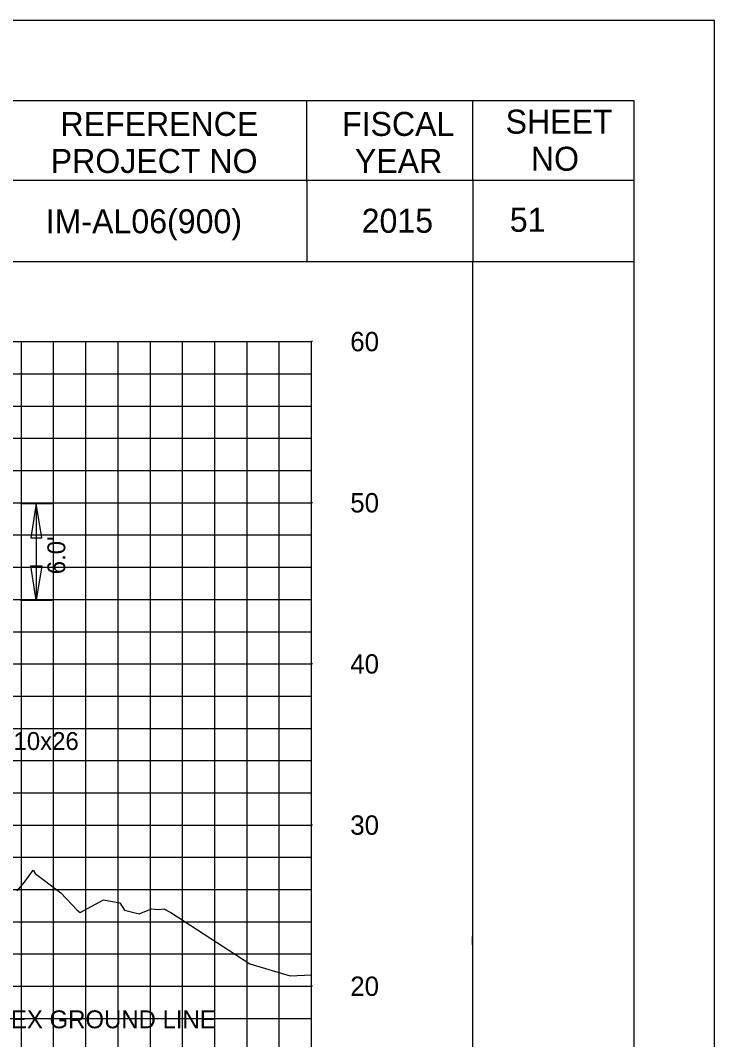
# Model space of a CAD drawing. Extents: x 2193008 to 2198143, y 1236112 to 1237864.
# Drawn here: x 2195154.8 to 2195197.9, y 1237274.8 to 1237338 of the extents above; entities that cross this region are included whole.
import ezdxf

# ---------------------------------------------------------------- set-up
doc = ezdxf.new("R2010")
doc.units = 0
for name, color, linetype in [('2', 7, 'Continuous'), ('31', 7, 'Continuous'), ('60', 7, 'Continuous'), ('ANNO-SHT', 7, 'Continuous'), ('GSDIMS', 7, 'Continuous'), ('Level 55', 7, 'Continuous'), ('Level 6', 7, 'Continuous'), ('M-ROADS', 7, 'Continuous'), ('SHT-BNDRY', 7, 'Continuous')]:
    doc.layers.add(name, color=color, linetype=linetype)

msp = doc.modelspace()

# ---------------------------------------------------------------- linework, layer by layer
msp.add_lwpolyline([(2194882.86, 1237133.046), (2195182.86, 1237133.046), (2195182.86, 1237323.046), (2194882.86, 1237323.046)], close=True)
at = {"layer": '2'}
msp.add_lwpolyline([(2195182.826, 1237281.186), (2195182.835, 1237280.187)], dxfattribs=at)
msp.add_lwpolyline([(2195182.826, 1237281.186), (2195182.835, 1237280.187)], dxfattribs=at)
at = {"layer": '60'}
for p, q in [((2195172.86, 1237258.106), (2195172.86, 1237318.106)), ((2195172.92, 1237318.106), (2195172.86, 1237318.106)), ((2195172.92, 1237308.106), (2195172.86, 1237308.106)), ((2195172.92, 1237298.106), (2195172.86, 1237298.106)), ((2195172.92, 1237288.106), (2195172.86, 1237288.106)), ((2195172.92, 1237278.106), (2195172.86, 1237278.106))]:
    msp.add_line(p, q, dxfattribs=at)
at = {"layer": 'GSDIMS'}
for p, q in [((2195154.801, 1237308.062), (2195156.769, 1237308.062)), ((2195155.785, 1237308.062), (2195155.785, 1237302.068)), ((2195154.801, 1237302.068), (2195156.769, 1237302.068))]:
    msp.add_line(p, q, dxfattribs=at)
for points in [[(2195155.785, 1237308.062), (2195155.437, 1237305.934), (2195156.132, 1237305.934)], [(2195155.785, 1237302.068), (2195155.437, 1237304.197), (2195156.132, 1237304.197)]]:
    msp.add_lwpolyline(points, close=True, dxfattribs=at)
at = {"layer": 'Level 6'}
for p, q in [((2195172.57, 1237328.038), (2195172.57, 1237333.038)), ((2195182.86, 1237328.168), (2195182.86, 1237333.038)), ((2195192.863, 1237328.097), (2195153.407, 1237328.097)), ((2195182.86, 1237328.168), (2195182.86, 1237323.046)), ((2195172.57, 1237328.038), (2195172.57, 1237323.046)), ((2195192.863, 1237323.046), (2195154.617, 1237323.046))]:
    msp.add_line(p, q, dxfattribs=at)
at = {"layer": 'M-ROADS'}
for p, q in [((2195042.86, 1237318.106), (2195172.86, 1237318.106)), ((2195154.86, 1237258.106), (2195154.86, 1237318.106)), ((2195156.86, 1237258.106), (2195156.86, 1237318.106)), ((2195158.86, 1237258.106), (2195158.86, 1237318.106)), ((2195160.86, 1237258.106), (2195160.86, 1237318.106)), ((2195162.86, 1237258.106), (2195162.86, 1237318.106)), ((2195164.86, 1237258.106), (2195164.86, 1237318.106)), ((2195166.86, 1237258.106), (2195166.86, 1237318.106)), ((2195168.86, 1237258.106), (2195168.86, 1237318.106)), ((2195170.86, 1237258.106), (2195170.86, 1237318.106)), ((2195172.86, 1237258.106), (2195172.86, 1237318.106)), ((2195042.86, 1237316.106), (2195172.86, 1237316.106)), ((2195042.86, 1237314.106), (2195172.86, 1237314.106)), ((2195042.86, 1237312.106), (2195172.86, 1237312.106)), ((2195042.86, 1237310.106), (2195172.86, 1237310.106)), ((2195042.86, 1237308.106), (2195172.86, 1237308.106)), ((2195042.86, 1237306.106), (2195172.86, 1237306.106)), ((2195042.86, 1237304.106), (2195172.86, 1237304.106)), ((2195042.86, 1237302.106), (2195172.86, 1237302.106)), ((2195042.86, 1237300.106), (2195172.86, 1237300.106)), ((2195042.86, 1237298.106), (2195172.86, 1237298.106)), ((2195042.86, 1237296.106), (2195172.86, 1237296.106)), ((2195042.86, 1237294.106), (2195172.86, 1237294.106)), ((2195042.86, 1237292.106), (2195172.86, 1237292.106)), ((2195042.86, 1237290.106), (2195172.86, 1237290.106)), ((2195042.86, 1237288.106), (2195172.86, 1237288.106)), ((2195042.86, 1237286.106), (2195172.86, 1237286.106)), ((2195042.86, 1237284.106), (2195172.86, 1237284.106)), ((2195042.86, 1237282.106), (2195172.86, 1237282.106)), ((2195042.86, 1237280.106), (2195172.86, 1237280.106)), ((2195042.86, 1237278.106), (2195172.86, 1237278.106)), ((2195042.86, 1237276.106), (2195172.86, 1237276.106))]:
    msp.add_line(p, q, dxfattribs=at)
msp.add_lwpolyline([(2194857.863, 1237118.036), (2195197.863, 1237118.036), (2195197.863, 1237338.036), (2194857.863, 1237338.036)], close=True, dxfattribs=at)
msp.add_lwpolyline([(2195154.606, 1237284.035), (2195155.051, 1237284.565), (2195155.585, 1237285.306), (2195155.708, 1237285.106), (2195157.303, 1237283.896), (2195158.326, 1237282.821), (2195158.506, 1237282.691), (2195159.959, 1237283.461), (2195160.961, 1237283.278), (2195161.256, 1237282.831), (2195162.156, 1237282.593), (2195162.938, 1237282.916), (2195163.394, 1237282.863), (2195163.696, 1237282.916), (2195164.128, 1237282.677), (2195169.033, 1237279.491), (2195171.54, 1237278.746), (2195172.86, 1237278.815)], dxfattribs=at)
at = {"layer": 'SHT-BNDRY'}
msp.add_lwpolyline([(2194870.363, 1237123.036), (2195192.863, 1237123.036), (2195192.863, 1237333.036), (2194870.363, 1237333.036)], close=True, dxfattribs=at)

# ---------------------------------------------------------------- texts
at = {"layer": '31'}
for s, p in [('60', (2195175.26, 1237317.506)), ('50', (2195175.26, 1237307.506)), ('40', (2195175.26, 1237297.506)), ('30', (2195175.26, 1237287.506)), ('20', (2195175.26, 1237277.506))]:
    msp.add_text(s, height=1.2, dxfattribs=at).set_placement(p)
at = {"layer": 'ANNO-SHT'}
for s, height, p in [(' IM-AL06(900) ', 1.48986, (2195155.813, 1237324.827)), ('2015', 1.4899, (2195175.967, 1237324.858)), ('  51 ', 1.4899, (2195184.051, 1237324.918))]:
    msp.add_text(s, height=height, rotation=360, dxfattribs=at).set_placement(p)
at = {"layer": 'Level 55'}
msp.add_text("6.0'", height=1.1105, rotation=90, dxfattribs=at).set_placement((2195157.582, 1237303.67))
for s, height, p in [('W10x26', 1.1105, (2195152.969, 1237292.765)), ('EX GROUND LINE', 1.11046, (2195154.21, 1237275.497))]:
    msp.add_text(s, height=height, dxfattribs=at).set_placement(p)
at = {"layer": 'Level 6'}
for s, p in [('SHEET', (2195184.897, 1237331.008)), ('REFERENCE', (2195157.28, 1237330.868)), ('FISCAL', (2195174.75, 1237330.868)), ('PROJECT NO', (2195156.68, 1237328.568)), ('YEAR', (2195175.55, 1237328.568)), ('NO', (2195186.467, 1237328.708))]:
    msp.add_text(s, height=1.4883, dxfattribs=at).set_placement(p)

doc.saveas('drawing.dxf')
